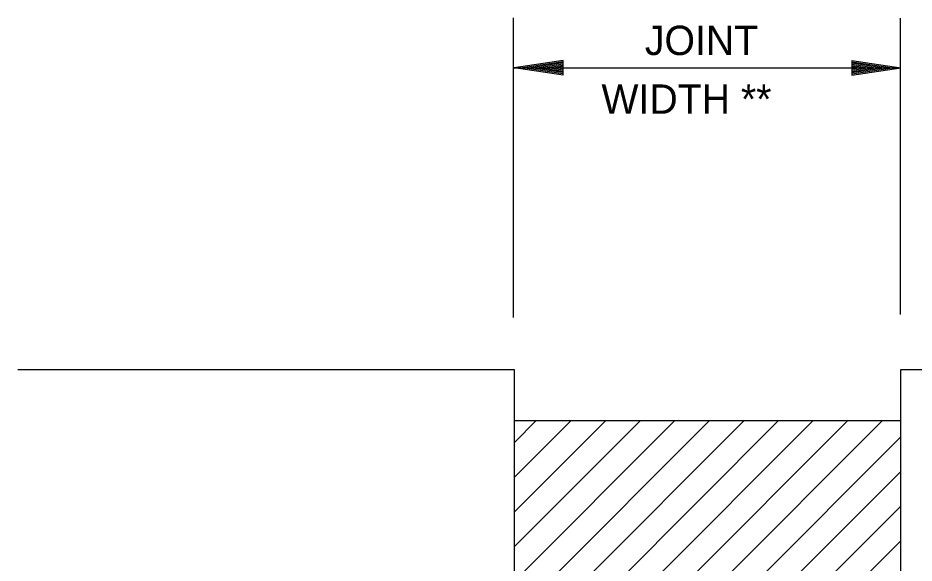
# Model space of a CAD drawing. Extents: x 1375738 to 1375905, y 380661 to 380875.
# Drawn here: x 1375833.55 to 1375851.88, y 380718.31 to 380729.45 of the extents above; entities that cross this region are included whole.
import ezdxf

# ---------------------------------------------------------------- set-up
doc = ezdxf.new("R2010")
doc.units = 0
doc.layers.add('R_Draft', color=7, linetype='Continuous')

msp = doc.modelspace()

# ---------------------------------------------------------------- linework, layer by layer
at = {"layer": 'R_Draft'}
for p, q in [((1375843.69, 380723.327), (1375843.69, 380729.449)), ((1375851.601, 380723.389), (1375851.601, 380729.443)), ((1375844.702, 380728.58), (1375843.702, 380728.43)), ((1375844.702, 380728.555), (1375843.869, 380728.43)), ((1375844.702, 380728.53), (1375844.041, 380728.43)), ((1375844.702, 380728.505), (1375844.208, 380728.43)), ((1375844.702, 380728.479), (1375844.377, 380728.43)), ((1375844.702, 380728.28), (1375844.702, 380728.58)), ((1375850.607, 380728.58), (1375851.607, 380728.43)), ((1375850.607, 380728.58), (1375850.607, 380728.28)), ((1375850.607, 380728.555), (1375851.44, 380728.43)), ((1375850.607, 380728.53), (1375851.268, 380728.43)), ((1375850.607, 380728.505), (1375851.101, 380728.43)), ((1375850.607, 380728.479), (1375850.932, 380728.43)), ((1375843.702, 380728.43), (1375851.607, 380728.43)), ((1375844.702, 380728.28), (1375843.702, 380728.43)), ((1375844.702, 380728.305), (1375843.869, 380728.43)), ((1375844.702, 380728.331), (1375844.041, 380728.43)), ((1375844.702, 380728.356), (1375844.208, 380728.43)), ((1375844.702, 380728.382), (1375844.377, 380728.43)), ((1375844.702, 380728.454), (1375844.544, 380728.43)), ((1375844.702, 380728.407), (1375844.544, 380728.43)), ((1375850.607, 380728.454), (1375850.765, 380728.43)), ((1375850.607, 380728.28), (1375851.607, 380728.43)), ((1375850.607, 380728.381), (1375850.932, 380728.43)), ((1375850.607, 380728.331), (1375851.268, 380728.43)), ((1375850.607, 380728.305), (1375851.44, 380728.43)), ((1375850.607, 380728.356), (1375851.101, 380728.43)), ((1375850.607, 380728.407), (1375850.765, 380728.43)), ((1375833.553, 380722.262), (1375843.702, 380722.262)), ((1375843.702, 380722.262), (1375843.702, 380700.693)), ((1375851.607, 380700.693), (1375851.607, 380722.262)), ((1375851.607, 380722.262), (1375858.991, 380722.262)), ((1375843.702, 380717.224), (1375847.696, 380721.218)), ((1375843.702, 380716.517), (1375848.403, 380721.218)), ((1375843.702, 380715.81), (1375849.11, 380721.218)), ((1375843.702, 380715.103), (1375849.817, 380721.218)), ((1375843.702, 380714.396), (1375850.524, 380721.218)), ((1375843.702, 380713.688), (1375851.232, 380721.218)), ((1375843.702, 380719.345), (1375845.575, 380721.218)), ((1375843.702, 380718.638), (1375846.282, 380721.218)), ((1375843.702, 380717.931), (1375846.989, 380721.218)), ((1375843.702, 380721.218), (1375851.607, 380721.218)), ((1375843.702, 380720.056), (1375844.864, 380721.218)), ((1375843.702, 380720.768), (1375844.153, 380721.218)), ((1375843.702, 380712.981), (1375851.607, 380720.886)), ((1375843.702, 380712.274), (1375851.607, 380720.179)), ((1375843.702, 380711.567), (1375851.607, 380719.472)), ((1375843.702, 380710.86), (1375851.607, 380718.765))]:
    msp.add_line(p, q, dxfattribs=at)

# ---------------------------------------------------------------- texts
for s, p in [('JOINT', (1375846.374, 380728.691)), (' WIDTH **', (1375845.264, 380727.491))]:
    msp.add_text(s, height=0.6, dxfattribs=at).set_placement(p)

doc.saveas('drawing.dxf')
